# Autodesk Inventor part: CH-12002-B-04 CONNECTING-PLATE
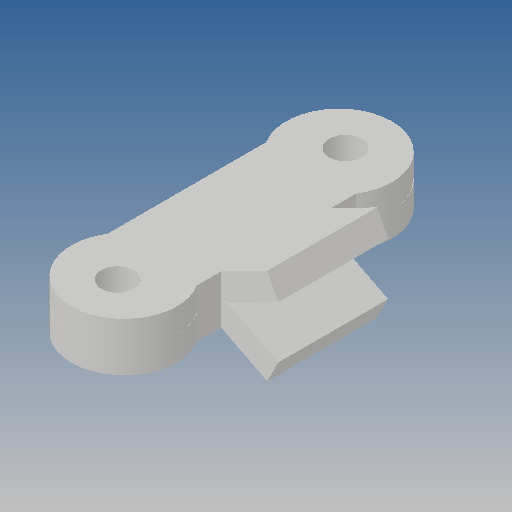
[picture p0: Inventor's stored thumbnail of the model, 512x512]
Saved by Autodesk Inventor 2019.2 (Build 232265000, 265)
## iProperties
Created: 2012-09
Part Number: CH-12002-B-04 CONNECTING-PLATE
Material: Ogólny
Document SubType Name: Modeling
Designer: CADENGINEERING4
Density: 1 g/cm^3
Appearance: Domyślna
Author: CADENGINEERING4
Revision Number: ÈÎºÎ
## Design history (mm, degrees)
feature "ÇÐ³ý-À­Éì8[1]"
feature "ÇÐ³ý-À­Éì8[2]"
node "Bryła1"
node "Bryła2"
